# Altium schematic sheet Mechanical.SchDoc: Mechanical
size A4; Date: Not used; ApprovedBy: Not used; CheckedBy: Not used; Author: Not used; CompanyName: STMicroelectronics; DrawnBy: Not used; Engineer: Not used; Organization: Not used; Address1: Not used; Address2: Not used; Address3: Not used; Address4: Not used; DocumentNumber: 8; Revision: Not used; SheetNumber: 8; SheetTotal: 8
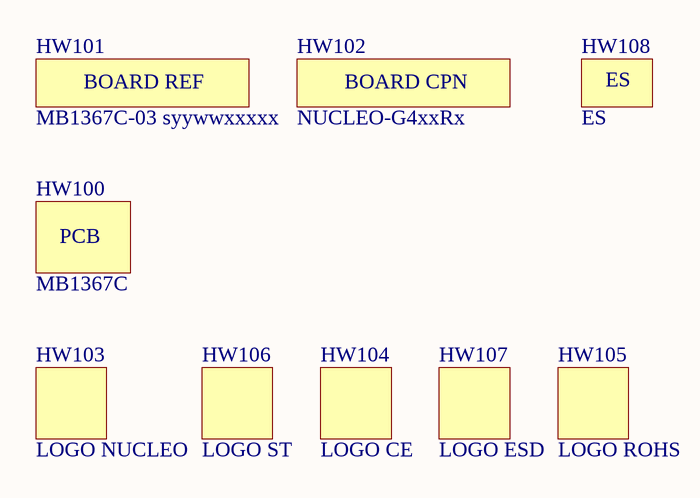
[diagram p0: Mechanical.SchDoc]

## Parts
HW100  value MB1367C  (mechanical)
HW101  value MB1367C-03 syywwxxxxx  [STICKER_BOARD-REF_25X5]  (mechanical)
HW102  value NUCLEO-G4xxRx  (mechanical)
HW103  value LOGO NUCLEO  [LOGO_NUCLEO]  (no BOM)
HW104  value LOGO CE  [LOGO_CE]  (no BOM)
HW105  value LOGO ROHS  [LOGO_ROHS]  (no BOM)
HW106  value LOGO ST  [LOGO_ST]  (no BOM)
HW107  value LOGO ESD  [LOGO_MAIN_1]  (no BOM)
HW108  value ES  (hidden comment: STICKER_ES)  (mechanical)

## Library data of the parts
HW100 = MCD-00216: PCB, xxxx for PCB ref, Y for revision; Part_Type: Mechanical; Provided_By: Subcon; Initial_Board_Reference: MB1319
HW101 = MCD-00235: Board sticker to mention board reference + serial number + QR code; Part_Type: Mechanical; Manufacturer_Part_Number: NA; Provided_By: Subcon; Initial_Board_Reference: MB1319
HW102 = MCD-00549: Product sticker to mention product CPN + product FG; Part_Type: Mechanical; Provided_By: Subcon; Initial_Board_Reference: MB1319
HW103 = MCD-00636: "NUCLEO" logo footprint for PCB; Part_Type: Mechanical; Initial_Board_Reference: MB1331
HW104 = MCD-00626: "CE" logo footprint for PCB; Part_Type: Mechanical; Initial_Board_Reference: MB1331
HW105 = MCD-00628: "ROHS" logo footprint for PCB; Part_Type: Mechanical; Initial_Board_Reference: MB1331
HW106 = MCD-00625: "STMicroelectronics" logo footprint for PCB; Part_Type: Mechanical; Initial_Board_Reference: MB1331
HW107 = MCD-00627: "Hand" ESD logo footprint for PCB; Part_Type: Mechanical; Initial_Board_Reference: MB1331
HW108 = MCD-00234: Sticker to mention ES sample; Part_Type: Mechanical; Provided_By: Subcon; Initial_Board_Reference: MB1319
